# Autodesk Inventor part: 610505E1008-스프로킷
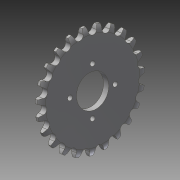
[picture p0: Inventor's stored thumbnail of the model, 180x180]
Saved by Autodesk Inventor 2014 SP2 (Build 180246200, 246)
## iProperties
Created: 2021-05
Part Number: 610505E1008-스프로킷
Material: 강철
Document SubType Name: Modeling
Designer: 거성
Mass: 261.628 g
Surface Area: 150.37 cm^2
Volume: 33.3284 cm^3
Density: 7.85 g/cm^3
Appearance: 강철
Author: 거성
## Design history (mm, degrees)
sketch "스케치1"
  geometry: L1 (-2.9, 0)-(2.9, 0); L2 (-2.9, 15)-(2.9, 15); L3 (-2.9, 15)-(-2.9, 43.625); L4 (-1.3, 50)-(1.3, 50); L5 (2.9, 15)-(2.9, 43.625); A1 r 13.5 centre (10.6, 43.625) between (-1.3, 50) and (-2.9, 43.625); A2 r 13.5 centre (-10.6, 43.625) between (2.9, 43.625) and (1.3, 50); 4 further points
  constraints: 10 end point, 4 point on circle, 4 vertical alignment, 3 parallel, 2 centre point, 2 point on line, 2 tangent, 1 coincident, 1 equal radius, 1 horizontal, 1 midpoint
  dimensions: "d0" = 5.8 distance of L1.start L1.end; "d2" = 100 diameter of L4 L1; "d3" = 13.5 radius of A1; "d4" = 2.6 distance of L4.start L4.end; "d5" = 87.2501 diameter of A2.centre L1 (derived); "d7" = 30 diameter of L2 L1
revolve "회전1" sketch "스케치1" stored, may be unused: angle "d8" = 90 deg
sketch "스케치2"
  geometry: L1 (0, 0)-(0, 50); C1 r 15 at (0, 0) reference; C2 r 42.75 at (0, 0); C3 r 43.625 at (0, 0) reference; A1 r 46.635 centre (0, 0) between (0, 46.635) and (-16.321, 43.686); A2 r 3.885 centre (0, 46.635) between (-3.823, 45.944) and (3.823, 45.944); A3 r 12.7 centre (-16.321, 43.686) between (-3.823, 45.944) and (-5.153, 49.734); A4 r 12.7 centre (16.321, 43.686) between (5.153, 49.734) and (3.823, 45.944); A5 r 50 centre (0, 0) between (5.153, 49.734) and (-5.153, 49.734); 2 further points
  constraints: 10 point on circle, 6 centre point, 3 coincident, 3 symmetric about line, 2 end point, 1 point on line, 1 tangent, 1 vertical, 1 vertical alignment, 4 other
  dimensions: "d9" = 93.27 diameter of A1; "d10" = 85.5 diameter of C2; "d13" = 7.77 diameter of A2; "d14" = 12.7 radius of A3
extrude "돌출1" cut sketch "스케치2" stored distance "d15" = 10; taper "d16" = 0 deg
sketch "스케치3"
  geometry: L1 (0, -46.635)-(0, -25.635); C1 r 15 at (0, -46.635) reference; 1 further point
  constraints: 2 end point, 1 coincident, 1 vertical
  dimensions: "d20" = 21 distance of L1.start L1.end
hole "구멍1" sketch "스케치3" at (0, -25.635) diameter "d21" = 4.5; stored, may be unused: countersink angle "d25" = 90 deg, drill point angle "d27" = 118 deg; dims "d22" = 6, "d23" = 4, "d24" = 2, "d26" = 8
node "솔리드1"
pattern_circular "원형 패턴1" dims angle "d18" = 360 deg
pattern_circular "원형 패턴2" dims angle "d29" = 360 deg
node "투영된 루프1"
other parameters: "d11" = 7.77
